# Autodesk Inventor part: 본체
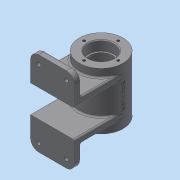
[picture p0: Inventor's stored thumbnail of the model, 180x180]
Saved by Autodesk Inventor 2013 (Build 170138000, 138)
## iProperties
Created: 2017-02
Part Number: 본체
Material: 일반
Document SubType Name: Modeling
Designer: dgall
Density: 1 g/cm^3
Author: dgall
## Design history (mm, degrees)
sketch "스케치1"
  geometry: C1 r 27 at (0, 0); 1 further point
  constraints: 1 centre point, 1 coincident
  dimensions: "d0" = 54 diameter of C1
extrude "돌출1" new body sketch "스케치1" stored distance "d2" = 70; taper "d3" = 0 deg
sketch "스케치2"
  geometry: L1 (-52, 52)-(-60, 52); L2 (-60, 52)-(-60, 17); L3 (-60, 17)-(-52, 17); L4 (-52, 17)-(-52, 52); 1 further point
  constraints: 8 end point, 2 parallel, 1 horizontal, 1 perpendicular
  dimensions: "d4" = 17 distance from line of L3 point (0, 0); "d5" = 52 distance from line of L1 point (0, 0); "d6" = 8 distance of L1.start L1.end; "d7" = 60 distance from line of point (0, 0) L2
extrude "돌출2" join sketch "스케치2" stored distance "d8" = 54; taper "d9" = 0 deg
node "작업 평면1"
sketch "스케치3"
  geometry: L1 (27, -52)-(-27, -52) reference; L2 (-27, 0)-(-27, -52); L3 (27, 0)-(27, -52); A1 r 27 centre (0, 0) between (-27, 0) and (27, 0) reference; 1 further point
  constraints: 4 end point, 2 point on circle, 2 tangent, 1 parallel, 1 perpendicular
extrude "돌출3" join sketch "스케치3" distance "d11" = 8; taper "d12" = 0 deg
fillet "모깎기1" dims "d13" = 10
node "작업 평면2"
sketch "스케치4"
  geometry: L1 (27, 35)-(-27, 35) reference; C1 r 5 at (0, 10); 1 further point
  constraints: 1 centre point, 1 vertical alignment
  dimensions: "d15" = 25 distance from line of C1.centre L1; "d31" = 10 diameter of C1
extrude "돌출4" join sketch "스케치4" stored distance "d16" = 8; taper "d17" = 0 deg
sketch "스케치5"
  geometry: L1 (0, 0)-(-16.339, -25.16); L2 (0, 0)-(0, -27); 1 further point
  constraints: 4 end point, 1 vertical, 1 vertical alignment, 1 other
  dimensions: "d18" = 33 deg angle of L1 L2; "d19" = 30 distance of L1.start L1.end
node "작업 평면3"
sketch "스케치6"
  geometry: C1 r 6 at (0, 0); 1 further point
  constraints: 1 centre point, 1 coincident
  dimensions: "d20" = 12 diameter of C1
extrude "돌출5" join sketch "스케치6" stored distance "d22" = 8; taper "d23" = 0 deg
sketch "스케치7"
  geometry: L1 (27, 35)-(-27, 35) reference; L2 (-27, -35)-(27, -35) reference; L3 (0, 35)-(0, -35); L4 (0, 35)-(16, 35); L5 (16, 35)-(16, 23); L6 (16, 23)-(14, 23); L7 (14, 23)-(14, 20); L8 (14, 20)-(22, 20); L9 (22, 20)-(22, -20); L10 (22, -20)-(14, -20); L11 (14, -20)-(14, -23); L12 (14, -23)-(16, -23); L13 (16, -23)-(16, -35); 1 further point
  constraints: 22 end point, 6 parallel, 3 perpendicular, 2 collinear, 2 midpoint, 2 point on line, 2 vertical alignment
  dimensions: "d24" = 12 distance of L4.end L5.end; "d26" = 3 distance of L6.end L7.end; "d27" = 28 diameter of L7 L3; "d28" = 32 diameter of L5 L3; "d29" = 44 diameter of L9 L3
revolve "회전1" sketch "스케치7" stored, may be unused: angle "d30" = 90 deg
hole "구멍1" diameter "d34" = 5.188; stored, may be unused: countersink angle "d38" = 90 deg, drill point angle "d40" = 118 deg; dims "d32" = 10, "d33" = 10, "d35" = 6, "d36" = 4, "d37" = 2, "d39" = 8
hole "구멍2" diameter "d43" = 5.188; stored, may be unused: countersink angle "d47" = 90 deg, drill point angle "d49" = 118 deg; dims "d41" = 10, "d42" = 10, "d44" = 6, "d45" = 4, "d46" = 2, "d48" = 8
sketch "스케치8"
  geometry: C1 r 16 at (0, 0) reference; C2 r 14 at (0, 0) reference; 1 further point
  constraints: 1 vertical alignment
  dimensions: "d50" = 21 distance of point (0, 21) C2.centre
hole "구멍3" sketch "스케치8" at (0, 21) diameter "d51" = 3.242; stored, may be unused: countersink angle "d55" = 90 deg, drill point angle "d57" = 118 deg; dims "d52" = 8, "d53" = 4, "d54" = 2, "d56" = 10
sketch "스케치9"
  geometry: L1 (10, 22.196)-(14.5, 19.598); L2 (14.5, 19.598)-(14.5, 14.402); L3 (14.5, 14.402)-(10, 11.804); L4 (10, 11.804)-(5.5, 14.402); L5 (5.5, 14.402)-(5.5, 19.598); L6 (5.5, 19.598)-(10, 22.196); C1 r 4.5 at (10, 17); A1 r 10 centre (10, 17) between (10, 27) and (0, 17) reference; 2 further points
  constraints: 12 end point, 2 coincident, 1 centre point, 1 tangent, 1 vertical alignment, 13 other
  dimensions: "d61" = 9 diameter of C1
extrude "돌출6" cut sketch "스케치9" distance "d63" = 3; taper "d64" = 0 deg
sketch "스케치10"
  geometry: A1 r 10 centre (10, 17) between (10, 27) and (0, 17) reference; 1 further point
hole "구멍4" sketch "스케치10" at (10, 17) diameter "d65" = 5; stored, may be unused: countersink angle "d69" = 90 deg, drill point angle "d71" = 118 deg; dims "d66" = 8, "d67" = 4, "d68" = 2, "d70" = 10
chamfer "모따기1" distance "d78" = 1; stored, may be unused: second distance "d79" = 2, angle "d80" = 45 deg
fillet "모깎기2" dims "d81" = 0.3, "d82" = 3
fillet "모깎기3" dims "d83" = 2
fillet "모깎기4" dims "d84" = 2
fillet "모깎기5" dims "d85" = 2
fillet "모깎기6" dims "d86" = 2
node "작업 평면4"
sketch "스케치11"
  geometry: L1 (27, 35)-(-27, 35) reference; 2 further points
  constraints: 1 other
  dimensions: "d88" = 35 distance from line of point (0, 0) L1; "d89" = 27 horizontal distance of point (0, 0) L1.start
feature "엠보싱1" sketch "스케치11" dims "d90" = 0.5, "d91" = 0
node "솔리드1"
mirror "대칭1"
pattern_circular "원형 패턴1" dims angle "d59" = 360 deg
mirror "대칭2"
pattern_linear "직사각형 패턴1" dims "d74" = 34, "d77" = 84
other parameters: "d10" = 17, "d14" = 32
